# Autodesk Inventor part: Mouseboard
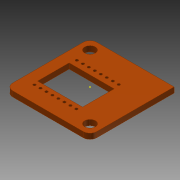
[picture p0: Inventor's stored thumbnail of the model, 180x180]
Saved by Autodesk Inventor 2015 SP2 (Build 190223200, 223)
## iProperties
Created: 2015-10
Part Number: Mouseboard
Material: Phenolharz
Document SubType Name: Modeling
Designer: rYan
Mass: 2.63184 g
Surface Area: 26.7225 cm^2
Volume: 1.90713 cm^3
Density: 1.38 g/cm^3
Appearance: Glatt - hellorange
Author: rYan
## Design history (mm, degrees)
sketch "Skizze1"
  geometry: L1 (-12.5, 12.5)-(12.5, 12.5); L2 (12.5, 12.5)-(12.5, -12.5); L3 (12.5, -12.5)-(-12.5, -12.5); L4 (-12.5, -12.5)-(-12.5, 12.5); L5 (0, 17.5)-(0, -17.5) reference; L6 (-17.5, 0)-(17.5, 0) reference; L7 (-9.3, 3.1)-(4.1, 3.1); L8 (4.1, 3.1)-(4.1, -6.3); L9 (4.1, -6.3)-(-9.3, -6.3); L10 (-9.3, -6.3)-(-9.3, 3.1); 1 further point
  constraints: 16 end point, 4 parallel, 2 horizontal, 2 perpendicular, 2 other
  dimensions: "d0" = 25 distance of L1.start L1.end; "d1" = 25 distance of L1.end L2.end; "d19" = 9.4 distance of L7.end L8.end; "d20" = 13.4 distance of L7.start L7.end; "d25" = 3.2 distance between parallel lines of L4 L10; "d26" = 9.4 distance between parallel lines of L1 L7
extrude "Extrusion1" new body sketch "Skizze1" distance "d2" = 1.6; taper "d3" = 0 deg
sketch "Skizze2"
  geometry: L1 (-9.3, 3.1)-(-9.3, -6.3) reference; L2 (4.1, 3.1)-(-9.3, 3.1) reference; 2 further points
  dimensions: "d22" = 1.8 distance from line of point (-8.8, 4.9) L2; "d24" = 0.5 distance from line of point (-8.8, 4.9) L1
hole "Bohrung1" sketch "Skizze2" at (-8.8, 4.9) diameter "d6" = 0.8; stored, may be unused: countersink angle "d10" = 90 deg, drill point angle "d12" = 118 deg; dims "d7" = 6, "d8" = 4, "d9" = 2, "d11" = 8
pattern_linear "Rechteckige Anordnung1" dims "d15" = 1.78, "d18" = 12.6
sketch "Skizze3"
  geometry: 1 further point
sketch "Skizze4"
  geometry: L1 (12.5, 12.5)-(-12.5, 12.5) reference; L2 (-12.5, 12.5)-(-12.5, -12.5) reference; 3 further points
  dimensions: "d27" = 3 distance from line of point (-9.5, 9.5) L1; "d28" = 3 distance from line of point (-9.5, 9.5) L2; "d29" = 22 distance from line of point (9.5, -9.5) L1; "d30" = 22 distance from line of L2 point (9.5, -9.5)
hole "Bohrung2" sketch "Skizze4" at (9.5, -9.5), (-9.5, 9.5) diameter "d31" = 3.2; stored, may be unused: countersink angle "d35" = 90 deg, drill point angle "d37" = 118 deg; dims "d32" = 6, "d33" = 4, "d34" = 2, "d36" = 8
fillet "Rundung1" dims "d38" = 2
node "Volumenkörper1"
